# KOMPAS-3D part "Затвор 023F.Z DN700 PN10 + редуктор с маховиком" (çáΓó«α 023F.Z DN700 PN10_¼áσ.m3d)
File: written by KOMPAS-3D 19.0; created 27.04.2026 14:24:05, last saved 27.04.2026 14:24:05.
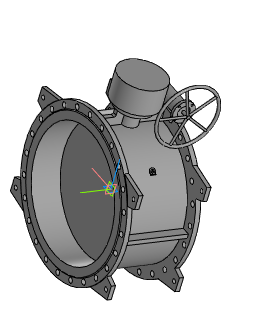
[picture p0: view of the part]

Document properties: Полное имя файла: ..\..\Затвор 023F.Z DN200-DN1600_с маховиком\Затвор 023F.Z DN700 PN10 + редуктор с маховиком.a3d

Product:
- Part/product: Затвор 023F.Z DN700 PN10 + редуктор с маховиком
    Масса: 562.99

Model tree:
1. Операция без истории:1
